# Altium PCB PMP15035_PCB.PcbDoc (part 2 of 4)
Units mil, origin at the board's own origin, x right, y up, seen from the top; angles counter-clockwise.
Board outline 5645 x 4585 mil, 8 copper layers (Top Layer, Signal Layer 1, Signal Layer 2, Signal Layer 3, Signal Layer 4, Signal Layer 5, Signal Layer 6, Bottom Layer), stack 60.9 mil thick; 335 components, 164 nets, 981 pads, 1349 vias.
Unrouted connection lines stored in the file: 46.
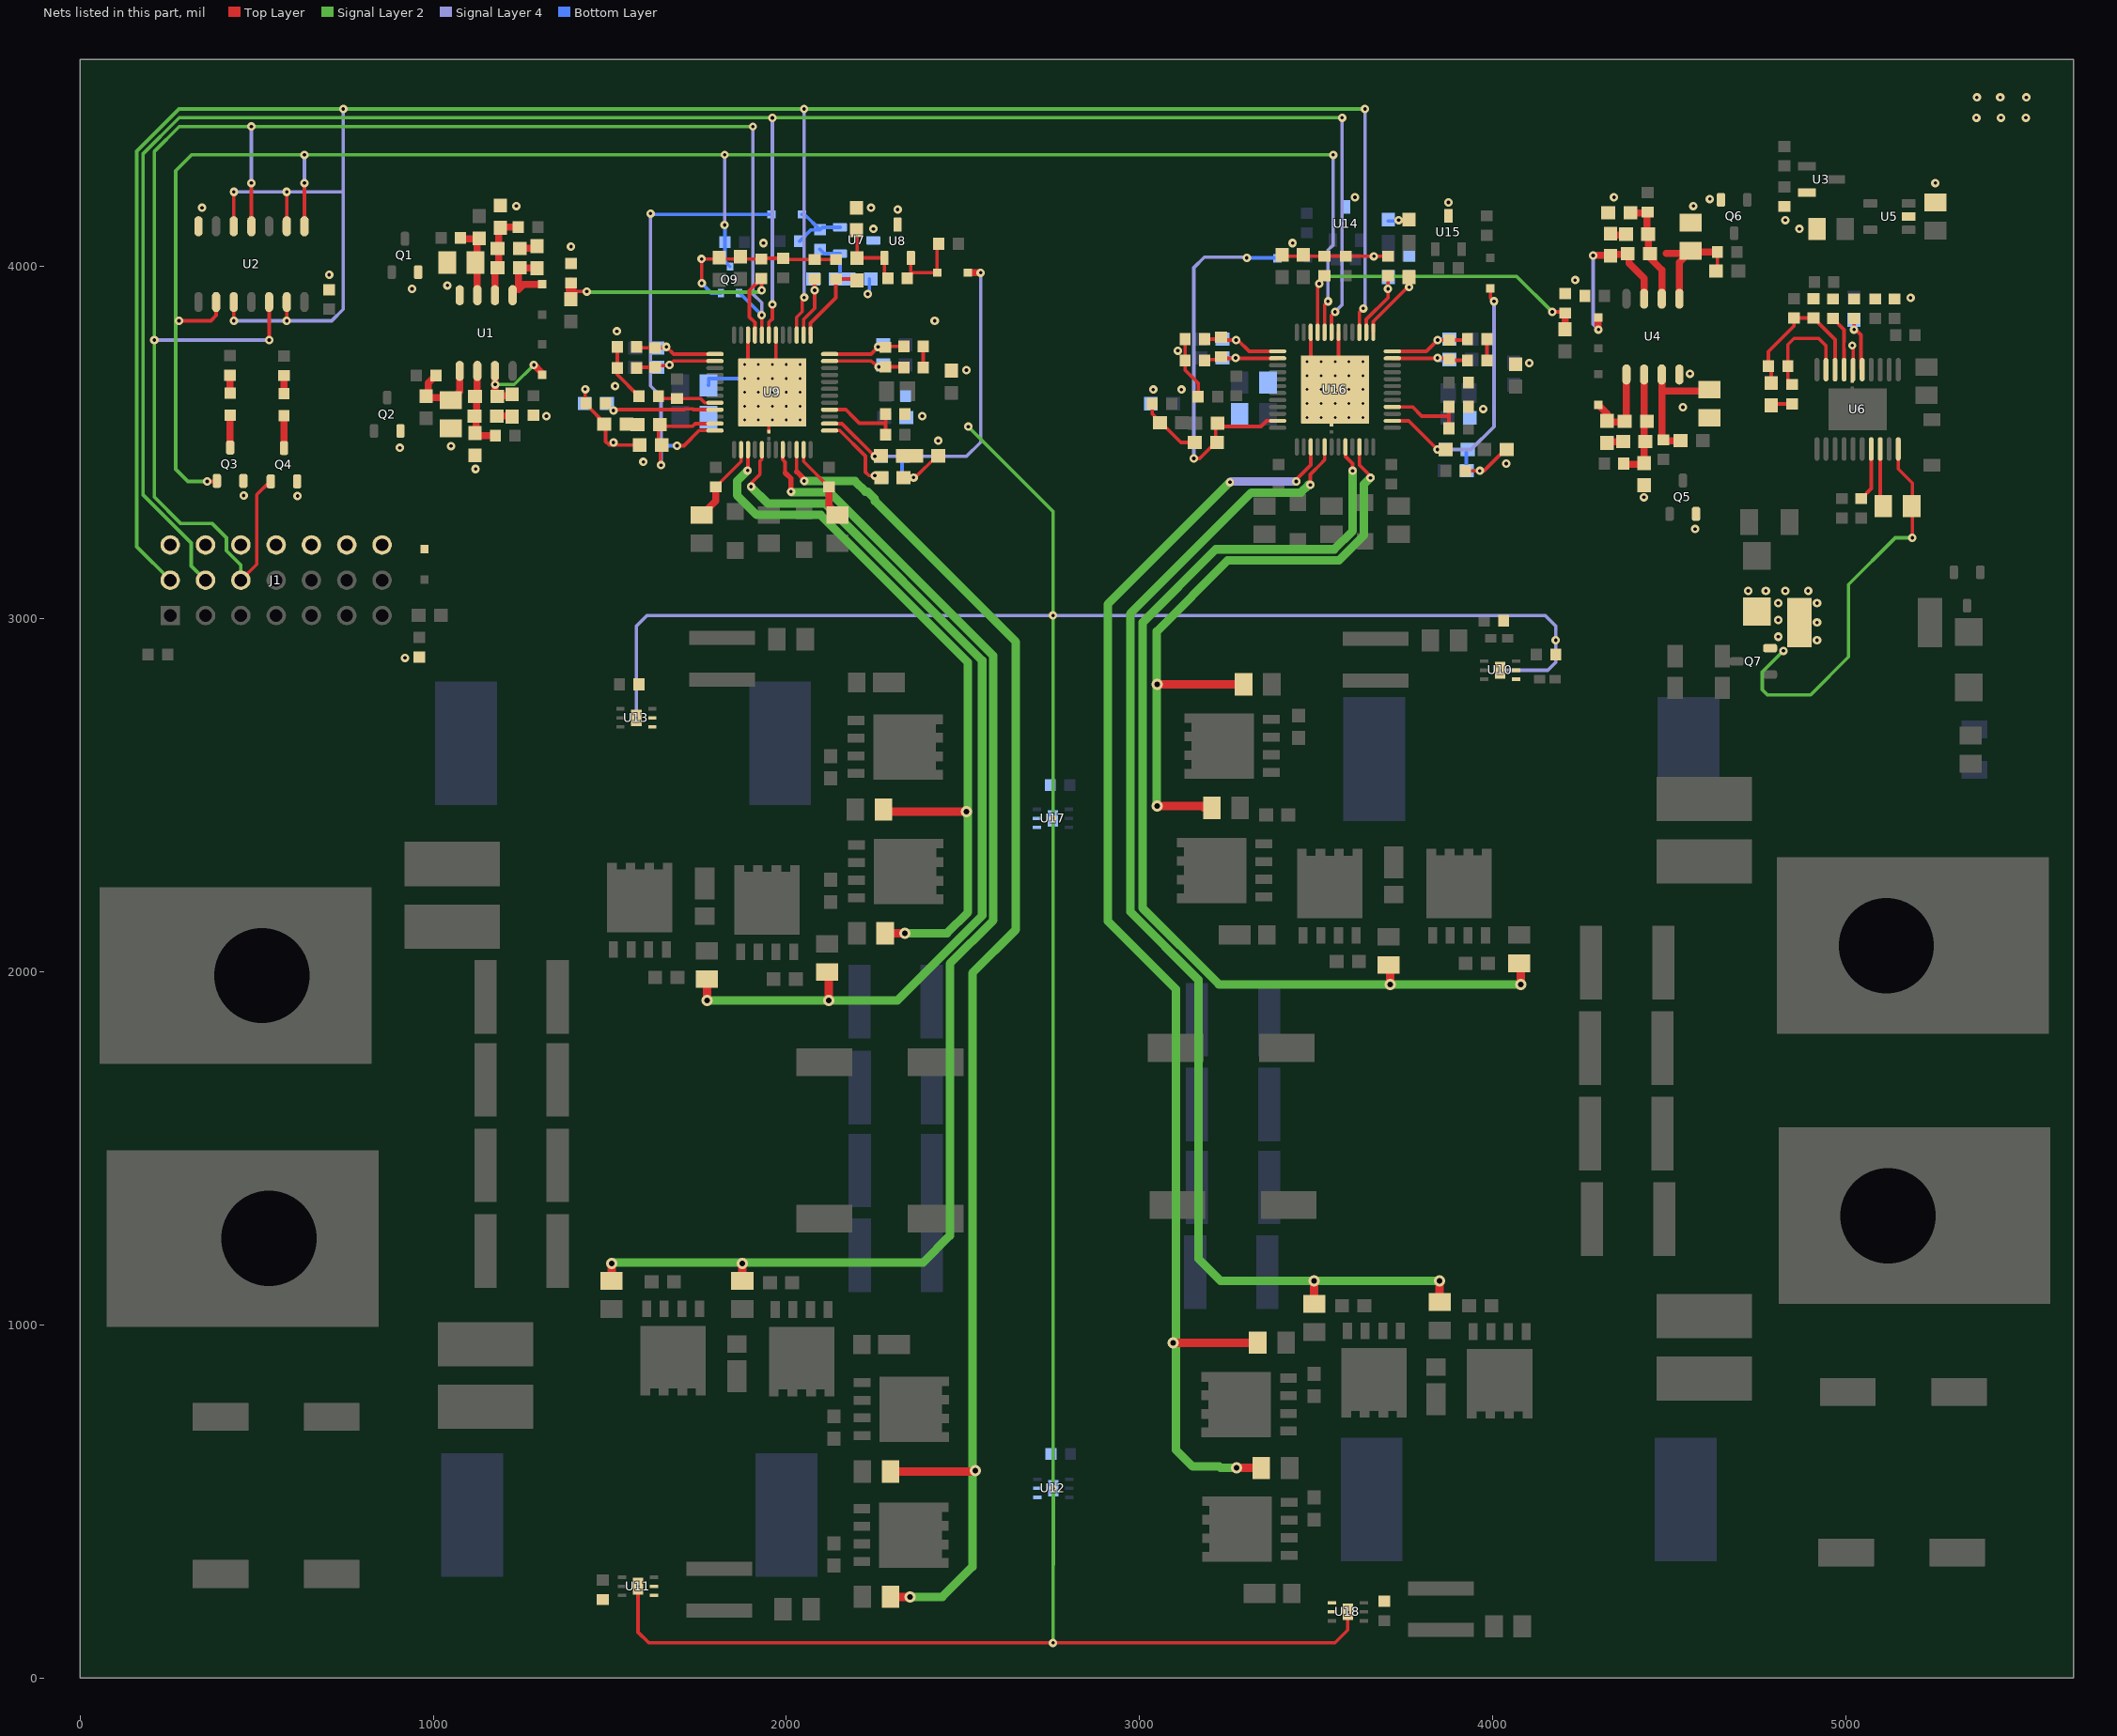
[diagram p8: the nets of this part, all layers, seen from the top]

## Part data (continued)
C8 C30 C31 C32 C36 C61 C62 C63 C66: library part CMP-0006993-4, "CAP, CERM, 1000 pF, 100 V, +/- 5%, C0G/NP0, 0603", Cap_Case=0603, Manufacturer=TDK, Supplier Part Number 1=445-2312-1-ND, TempCo=C0G/NP0, Tolerance_%=5%, Value1="0.0589 ohm", Value2=100V, ValueDisplayed=1000pF
C16 C17 C37 C38 C68 C69: "CAP, CERM, 1 µF, 100 V, +/- 10%, X7S, 0805", Cap_Case=0805, Manufacturer=TDK, Supplier Part Number 1=445-5205-1-ND, TempCo=X7S, Tolerance_%=10, Value1=Unknown, Value2=100V, ValueDisplayed=1µF
C18 C19: library part CMP-0009015-2, "CAP, CERM, 10 uF, 50 V, +/- 10%, X5R, AEC-Q200 Grade 1, 1206", Cap_Case=1206, Manufacturer=MuRata, Supplier Part Number 1=490-12456-1-ND, TempCo=X5R, Tolerance_%=10%, Value1=Unknown, Value2=50V, ValueDisplayed=10uF
C20 C21: library part CMP-0007886-2, "CAP, CERM, 0.1 uF, 100 V, +/- 10%, X7R, 0805", Cap_Case=0805, Manufacturer=TDK, Supplier Part Number 1=445-1418-1-ND, TempCo=X7R, Tolerance_%=10%, Value1="0.020726 ohm", Value2=100V, ValueDisplayed=0.1uF
C22 C45 C75: library part CMP-0007867-2, "CAP, CERM, 2.2 uF, 16 V, +/- 10%, X7R, 0805", Cap_Case=0805, Manufacturer=TDK, Supplier Part Number 1=445-1420-1-ND, TempCo=X7R, Tolerance_%=10%, Value1="0.0049 ohm", Value2=16V, ValueDisplayed=2.2uF
C23: library part CMP-0008653-2, "CAP, CERM, 47 uF, 16 V, +/- 15%, X5R, 1206", Cap_Case=1206, Manufacturer=TDK, Supplier Part Number 1=445-6003-1-ND, TempCo=X5R, Tolerance_%=15%, Value1=Unknown, Value2=16V, ValueDisplayed=47uF
C24: library part CMP-0007124-4, "CAP, CERM, 1800 pF, 25 V, +/- 10%, X7R, AEC-Q200 Grade 1, 0603", Cap_Case=0603, Manufacturer=MuRata, Supplier Part Number 1=81-GCJ216R71E182KA1D, TempCo=X7R, Tolerance_%=10%, Value1=Unknown, Value2=25V, ValueDisplayed=1800pF
C26: library part CMP-0007212-4, "CAP, CERM, 360 pF, 50 V, +/- 5%, C0G/NP0, 0603", Cap_Case=0603, Manufacturer=MuRata, Supplier Part Number 1=490-1440-1-ND, TempCo=C0G/NP0, Tolerance_%=5%, Value1=Unknown, Value2=50V, ValueDisplayed=360pF
C27 C28 C46 C77: "CAP, CERM, 1 µF, 25 V, +/- 10%, X7R, 0603", Cap_Case=0603, Manufacturer=MuRata, Supplier Part Number 1=490-5307-1-ND, TempCo=X7R, Tolerance_%=10, Value1=Unknown, Value2=25V, ValueDisplayed=1µF
C29: library part CMP-0007080-5, "CAP, CERM, 0.068 uF, 50 V, +/- 10%, X7R, AEC-Q200 Grade 1, 0603", Cap_Case=0603, Manufacturer=TDK, Supplier Part Number 1=445-5665-1-ND, TempCo=X7R, Tolerance_%=10%, Value1="0.035979 ohm", Value2=50V, ValueDisplayed=0.068uF
C33 C58 C64 C88: library part CMP-0006834-5, "CAP, CERM, 470 pF, 50 V, +/- 10%, X7R, 0603", Cap_Case=0603, Manufacturer="Wurth Elektronik", Supplier Part Number 1=710-885012206081, TempCo=X7R, Tolerance_%=10%, Value1=Unknown, Value2=50V, ValueDisplayed=470pF
C34 C54 C65 C85: library part CMP-0007423-4, "CAP, CERM, 0.047 uF, 25 V, +/- 10%, X7R, 0603", Cap_Case=0603, Manufacturer=MuRata, Supplier Part Number 1=490-1522-1-ND, TempCo=X7R, Tolerance_%=10%, Value1=Unknown, Value2=25V, ValueDisplayed=0.047uF
C35 C49 C50 C59 C67 C79 C80 C89: "CAP, CERM, 0.01 µF, 100 V, +/- 10%, X7R, 0603", Cap_Case=0603, Manufacturer=AVX, Supplier Part Number 1=478-1205-1-ND, TempCo=X7R, Tolerance_%=10, Value1="0.098 ohm", Value2=100V, ValueDisplayed=0.01µF
C39 C51 C70 C82: "CAP, CERM, 0.47 µF, 16 V, +/- 10%, X7R, 0603", Cap_Case=0603, Manufacturer=MuRata, Supplier Part Number 1=490-3295-1-ND, TempCo=X7R, Tolerance_%=10, Value1=Unknown, Value2=16V, ValueDisplayed=0.47µF
C40 C41 C52 C53 C56 C57 C60 C71 C72 C83 C84 C86 C87: "CAP, CERM, 100 pF, 50 V, +/- 5%, C0G/NP0, 0603", Cap_Case=0603, Manufacturer=Kemet, Supplier Part Number 1=399-1061-1-ND, TempCo=C0G/NP0, Tolerance_%=5, Value1=Unknown, Value2=50V, ValueDisplayed=100pF
C43 C48 C73 C78: "CAP, CERM, 0.22 µF, 50 V, +/- 10%, X7R, 0603", Cap_Case=0603, Manufacturer=TDK, Supplier Part Number 1=445-7408-1-ND, TempCo=X7R, Tolerance_%=10, Value1=Unknown, Value2=50V, ValueDisplayed=0.22µF
C92 C93 C110 C111: "CAP, CERM, 100 pF, 100 V, +/- 10%, C0G/NP0, 0805", Cap_Case=0805, Manufacturer=AVX, Supplier Part Number 1=478-3733-1-ND, TempCo=C0G/NP0, Tolerance_%=10, Value1="0.356 ohm", Value2=100V, ValueDisplayed=100pF
C94 C95 C96 C97 C102 C103 C104 C105 C112 C114 C115 C127: library part CMP-0012273-3, "CAP, Aluminum Polymer, 180 uF, 50 V, +/- 20%, 0.019 ohm, SMD, 2-Leads, Dia 10.5mm, Pin Spacing 8mm SMD", Cap_Case=10x12.7mm, Manufacturer=Nichicon, Supplier Part Number 1=493-13774-1-ND, Tolerance_%=20%, Value1="0.019 ohm", Value2=50V, ValueDisplayed=180uF
C98 C99 C100 C101 C106 C107 C108 C109 C116 C117 C118 C119 C121 C122 C123 C126: library part CMP-0009385-2, "CAP, CERM, 4.7 uF, 100 V, +/- 20%, X7R, 2220", Cap_Case=2220, Manufacturer=TDK, Supplier Part Number 1=445-1450-1-ND, TempCo=X7R, Tolerance_%=20%, Value1="0.0015 ohm", Value2=100V, ValueDisplayed=4.7uF
D1 D2 D5 D6 D10 D11 D16 D17: "Diode, Ultrafast, 75 V, 0.25 A, SOD-323", Manufacturer="Central Semiconductor", Value1=0.25A, Value2=1.2V
D7: library part CMP-0076974-1, "Diode, Switching, 100 V, 0.15 A, SOD-123", Manufacturer="Micro Commercial Components", Supplier Part Number 1=1N4148WTPMSCT-ND, Value1=0.15A, Value2=1.25V
D8 D9: library part CMP-0028585-1, "Diode, Schottky, 60 V, 1 A, SMA", Manufacturer="ON Semiconductor", Supplier Part Number 1=SS16T3GOSCT-ND, Value1=1A, Value2=0.72V
D12 D13 D18 D19: "Diode, Schottky, 60 V, 1 A, SOD-123F", Manufacturer="NXP Semiconductor", Supplier Part Number 1=568-4104-1-ND, Value1=1A, Value2=0.57V
D14: "Diode, Switching, 75 V, 0.3 A, SOD-523", Manufacturer="Micro Commercial Components", Supplier Part Number 1=1N4148XTPMSCT-ND, Value1=0.3A, Value2=1.25V
D15: library part CMP-0005865-1, "Diode, Zener, 5.1 V, 200 mW, SOD-323", Manufacturer="Diodes Inc.", Power_W=200mW, Supplier Part Number 1=BZT52C5V1S-FDICT-ND, Value1=0.2W
D21 D22 D23 D24 D25 D26 D27 D28: library part CMP-0028825-1, "Diode, Schottky, 60 V, 3 A, AEC-Q101, SOD-123HE", Manufacturer="Fairchild Semiconductor", Supplier Part Number 1=FSV360FPCT-ND, Value1=3A, Value2=0.65V
J1: library part CMP-0055099-1, "Header, 2.54 mm, 7x3, Gold, Vertical, TH", Color=Black, Manufacturer=Mill-Max, Supplier Part Number 1=ED8040-21-ND
L1: library part CMP-0061858-2, "Inductor, Shielded Drum Core, Ferrite, 150 uH, 1.16 A, 0.37 ohm, SMD", Manufacturer=Coilcraft, Value1="0.37 ohm", Value2=1.16A, ValueDisplayed=150uH
L8 L9 L10 L11: Alternate Manufacturer=-, Manufacturer="Used in BOM report"
NT1 NT2 NT3: "Single point connection between nets."
PGND PGND V12_A V12_B: "Terminal 70A Lug", Manufacturer=Panduit, Supplier Part Number 1=CXS70-14-C-ND
Q1 Q2 Q3 Q4 Q5 Q6: "MOSFET, N-CH, 60 V, 0.24 A, SOT-23", Alternate Manufacturer=None, Manufacturer=Vishay-Siliconix, Supplier Part Number 1=2N7002E-T1-E3CT-ND, Value1="1.8 ohm", Value2="0.4 nC"
Q7 Q8: library part CMP-0079125-1, "MOSFET, N-CH, 60 V, 2.3 A, AEC-Q101, SOT-23", Alternate Manufacturer=None, Manufacturer="Infineon Technologies", Supplier Part Number 1=BSR606NH6327XTSA1CT-ND, Value1="0.09 ohm", Value2="3.7 nC"
Q9: library part CMP-0000948-2, "MOSFET, N-CH, 100 V, 0.17 A, SOT-323", Alternate Manufacturer=None, Manufacturer="Diodes Inc.", Supplier Part Number 1=BSS123W-FDICT-ND, Value1=1
Q10 Q11 Q12 Q13 Q14 Q15 Q16 Q17 Q18 Q19 Q20 Q21 Q22 Q23 Q24 Q25: "MOSFET N-CH 60V SO8FL", Alternate Manufacturer=-, Input Capacitance=3.6nF, Manufacturer="Used in BOM report", Max Operating Temperature=175°C, Max Power Dissipation=3.7W, Min Operating Temperature=-55°C, Supplier Part Number 1=NVMFS5C628NLT1G**MULT1
R1 R17: library part CMP-0022841-3, "RES, 17.8 k, 1%, 0.1 W, 0603", Manufacturer="Yageo America", Power_W=100mW, Supplier Part Number 1=311-17.8KHRCT-ND, TempCo="200 ppm/C", Tolerance_%=1%, Value2=0.1W, Value_Code=17k8, ValueDisplayed=17.8k
R2 R16: library part CMP-0022360-3, "RES, 37.4 k, 1%, 0.1 W, 0603", Manufacturer=Vishay-Dale, Power_W=100mW, Supplier Part Number 1=541-37.4KHCT-ND, TempCo="100 ppm/C", Tolerance_%=1%, Value2=0.1W, Value_Code=37k4, ValueDisplayed=37.4k
R3 R19: library part CMP-0022986-3, "RES, 2.20 k, 1%, 0.1 W, 0603", Manufacturer="Yageo America", Power_W=100mW, Supplier Part Number 1=311-2.20KHRCT-ND, TempCo="200 ppm/C", Tolerance_%=1%, Value2=0.1W, Value_Code=2k20, ValueDisplayed=2.20k
R4 R18: library part CMP-0023279-3, "RES, 7.50 k, 1%, 0.1 W, 0603", Manufacturer="Yageo America", Power_W=100mW, Supplier Part Number 1=311-7.50KHRCT-ND, TempCo="200 ppm/C", Tolerance_%=1%, Value2=0.1W, Value_Code=7k50, ValueDisplayed=7.50k
R5 R21: library part CMP-0023332-3, "RES, 9.09 k, 1%, 0.1 W, 0603", Manufacturer="Yageo America", Power_W=100mW, Supplier Part Number 1=311-9.09KHRCT-ND, TempCo="200 ppm/C", Tolerance_%=1%, Value2=0.1W, Value_Code=9k09, ValueDisplayed=9.09k
R6 R20: library part CMP-0023195-3, "RES, 59.0 k, 1%, 0.1 W, 0603", Manufacturer="Yageo America", Power_W=100mW, Supplier Part Number 1=311-59.0KHRCT-ND, TempCo="200 ppm/C", Tolerance_%=1%, Value2=0.1W, Value_Code=59k0, ValueDisplayed=59.0k
R7 R22: library part CMP-0023141-3, "RES, 499, 1%, 0.1 W, 0603", Manufacturer="Yageo America", Power_W=100mW, Supplier Part Number 1=311-499HRCT-ND, TempCo="200 ppm/C", Tolerance_%=1%, Value2=0.1W, Value_Code=499R, ValueDisplayed=499
R8 R9 R23 R24: library part CMP-0022901-2, "RES, 200 k, 1%, 0.1 W, 0603", Manufacturer="Yageo America", Power_W=100mW, Supplier Part Number 1=311-200KHRCT-ND, TempCo="200 ppm/C", Tolerance_%=1%, Value2=0.1W, Value_Code=200k
R10 R25 R54 R79: "RES, 10.0 k, 1%, 0.1 W, 0603", Manufacturer=Vishay-Dale, Power_W=0.1, Supplier Part Number 1=541-10.0KHCT-ND, TempCo="100 ppm/C", Tolerance_%=1, Value1=1%, Value2=0.1W, Value_Code=10k0, ValueDisplayed=10.0k
R11 R12 R27 R28: "RES, 20.0, 1%, 0.1 W, 0603", Manufacturer=Vishay-Dale, Power_W=0.1, Supplier Part Number 1=541-20.0HCT-ND, TempCo="100 ppm/C", Tolerance_%=1, Value1=1%, Value2=0.1W, Value_Code=20R0, ValueDisplayed=20.0
R13 R14 R15 R40 R42 R66 R68: "RES, 4.99 k, 1%, 0.1 W, 0603", Manufacturer=Vishay-Dale, Power_W=0.1, Supplier Part Number 1=541-4.99KHCT-ND, TempCo="100 ppm/C", Tolerance_%=1, Value1=1%, Value2=0.1W, Value_Code=4k99, ValueDisplayed=4.99k
R30: "RES, 75.0 k, 1%, 0.1 W, 0603", Manufacturer=Vishay-Dale, Power_W=0.1, Supplier Part Number 1=541-75.0KHCT-ND, TempCo="100 ppm/C", Tolerance_%=1, Value1=1%, Value2=0.1W, Value_Code=75k0, ValueDisplayed=75.0k
R31: "RES, 29.4 k, 1%, 0.1 W, 0603", Manufacturer=Vishay-Dale, Power_W=0.1, Supplier Part Number 1=541-29.4KHCT-ND, TempCo="100 ppm/C", Tolerance_%=1, Value1=1%, Value2=0.1W, Value_Code=29k4, ValueDisplayed=29.4k
R32: library part CMP-0022866-3, "RES, 1.07 k, 1%, 0.1 W, 0603", Manufacturer="Yageo America", Power_W=100mW, Supplier Part Number 1=311-1.07KHRCT-ND, TempCo="200 ppm/C", Tolerance_%=1%, Value2=0.1W, Value_Code=1k07, ValueDisplayed=1.07k
R33: "RES, 18.2 k, 1%, 0.1 W, 0603", Manufacturer=Vishay-Dale, Power_W=0.1, Supplier Part Number 1=541-18.2KHCT-ND, TempCo="100 ppm/C", Tolerance_%=1, Value1=1%, Value2=0.1W, Value_Code=18k2, ValueDisplayed=18.2k
R34: library part CMP-0079171-1, "RES, 0.22, 1%, 0.5 W, 1206", Manufacturer="Susumu Co Ltd", Power_W=500mW, Supplier Part Number 1=28K1709, TempCo="100 ppm/C", Tolerance_%=1%, Value2=0.5W, Value_Code=R220, ValueDisplayed=0.22
R35: library part CMP-0022850-3, "RES, 18.2 k, 1%, 0.1 W, 0603", Manufacturer="Yageo America", Power_W=100mW, Supplier Part Number 1=311-18.2KHRCT-ND, TempCo="200 ppm/C", Tolerance_%=1%, Value2=0.1W, Value_Code=18k2, ValueDisplayed=18.2k
R36: "RES, 732, 1%, 0.1 W, 0603", Manufacturer=Vishay-Dale, Power_W=0.1, Supplier Part Number 1=541-732HCT-ND, TempCo="100 ppm/C", Tolerance_%=1, Value1=1%, Value2=0.1W, Value_Code=732R, ValueDisplayed=732
R37: "RES, 5.23 k, 1%, 0.1 W, 0603", Manufacturer=Vishay-Dale, Power_W=0.1, Supplier Part Number 1=541-5.23KHCT-ND, TempCo="100 ppm/C", Tolerance_%=1, Value1=1%, Value2=0.1W, Value_Code=5k23, ValueDisplayed=5.23k
R38: "RES, 10.0, 1%, 0.1 W, 0603", Manufacturer=Vishay-Dale, Power_W=0.1, Supplier Part Number 1=541-10.0HCT-ND, TempCo="100 ppm/C", Tolerance_%=1, Value1=1%, Value2=0.1W, Value_Code=10R0, ValueDisplayed=10.0
R39 R45 R65 R71: "RES, 95.3 k, 1%, 0.1 W, 0603", Manufacturer=Vishay-Dale, Power_W=0.1, Supplier Part Number 1=541-95.3KHCT-ND, TempCo="100 ppm/C", Tolerance_%=1, Value1=1%, Value2=0.1W, Value_Code=95k3, ValueDisplayed=95.3k
R41 R43 R67 R69: library part CMP-0022991-3, "RES, 2.40 k, 1%, 0.1 W, 0603", Manufacturer="Yageo America", Power_W=100mW, Supplier Part Number 1=311-2.40KHRCT-ND, TempCo="200 ppm/C", Tolerance_%=1%, Value2=0.1W, Value_Code=2k40, ValueDisplayed=2.40k
R44 R62 R70 R86: library part CMP-0022883-3, "RES, 1.50 k, 1%, 0.1 W, 0603", Manufacturer="Yageo America", Power_W=100mW, Supplier Part Number 1=311-1.50KHRCT-ND, TempCo="200 ppm/C", Tolerance_%=1%, Value2=0.1W, Value_Code=1k50, ValueDisplayed=1.50k
R46 R47 R72 R73: library part CMP-0022999-3, "RES, 2.94 k, 1%, 0.1 W, 0603", Manufacturer="Yageo America", Power_W=100mW, Supplier Part Number 1=311-2.94KHRCT-ND, TempCo="200 ppm/C", Tolerance_%=1%, Value2=0.1W, Value_Code=2k94, ValueDisplayed=2.94k
R48 R49 R63 R74 R75: library part CMP-0022906-3, "RES, 20.0 k, 1%, 0.1 W, 0603", Manufacturer="Yageo America", Power_W=100mW, Supplier Part Number 1=311-20.0KHRCT-ND, TempCo="200 ppm/C", Tolerance_%=1%, Value2=0.1W, Value_Code=20k0, ValueDisplayed=20.0k
R50: "RES, 100 k, 1%, 0.063 W, 0402", Manufacturer=Vishay-Dale, Power_W=0.063, Supplier Part Number 1=541-100KLCT-ND, TempCo="100 ppm/C", Tolerance_%=1, Value1=1%, Value2=0.063W, Value_Code=100k
R51: "RES, 49.9 k, 1%, 0.1 W, 0603", Manufacturer=Vishay-Dale, Power_W=0.1, Supplier Part Number 1=541-49.9KHCT-ND, TempCo="100 ppm/C", Tolerance_%=1, Value1=1%, Value2=0.1W, Value_Code=49k9, ValueDisplayed=49.9k
R52 R76: library part CMP-0023336-3, "RES, 9.76 k, 1%, 0.1 W, 0603", Manufacturer="Yageo America", Power_W=100mW, Supplier Part Number 1=311-9.76KHRCT-ND, TempCo="200 ppm/C", Tolerance_%=1%, Value2=0.1W, Value_Code=9k76, ValueDisplayed=9.76k
R53 R58 R77 R83: library part CMP-0021913-2, "RES, 2.00, 1%, 0.125 W, 0805", Manufacturer="Yageo America", Power_W=125mW, Supplier Part Number 1=311-2.00CRCT-ND, TempCo="200 ppm/C", Tolerance_%=1%, Value2=0.125W, Value_Code=2R00, ValueDisplayed=2.00
R55 R80: library part CMP-0023098-3, "RES, 40.2 k, 1%, 0.1 W, 0603", Manufacturer="Yageo America", Power_W=100mW, Supplier Part Number 1=311-40.2KHRCT-ND, TempCo="200 ppm/C", Tolerance_%=1%, Value2=0.1W, Value_Code=40k2, ValueDisplayed=40.2k
R56 R81: "RES, 24.9, 1%, 0.125 W, 0805", Manufacturer=Vishay-Dale, Power_W=0.125, Supplier Part Number 1=541-24.9CCT-ND, TempCo="100 ppm/C", Tolerance_%=1, Value1=1%, Value2=0.125W, Value_Code=24R9, ValueDisplayed=24.9
R57 R82: library part CMP-0023263-3, "RES, 73.2 k, 1%, 0.1 W, 0603", Manufacturer="Yageo America", Power_W=100mW, Supplier Part Number 1=311-73.2KHRCT-ND, TempCo="200 ppm/C", Tolerance_%=1%, Value2=0.1W, Value_Code=73k2, ValueDisplayed=73.2k
R59 R64: library part CMP-0022744-3, "RES, 10.5 k, 1%, 0.1 W, 0603", Manufacturer="Yageo America", Power_W=100mW, Supplier Part Number 1=311-10.5KHRCT-ND, TempCo="200 ppm/C", Tolerance_%=1%, Value2=0.1W, Value_Code=10k5, ValueDisplayed=10.5k
R60 R84: library part CMP-0023318-3, "RES, 91.0 k, 1%, 0.1 W, 0603", Manufacturer="Yageo America", Power_W=100mW, Supplier Part Number 1=311-91.0KHRCT-ND, TempCo="200 ppm/C", Tolerance_%=1%, Value2=0.1W, Value_Code=91k0, ValueDisplayed=91.0k
R61 R85: library part CMP-0023019-3, "RES, 30.9 k, 1%, 0.1 W, 0603", Manufacturer="Yageo America", Power_W=100mW, Supplier Part Number 1=311-30.9KHRCT-ND, TempCo="200 ppm/C", Tolerance_%=1%, Value2=0.1W, Value_Code=30k9, ValueDisplayed=30.9k
R87 R99 R111 R123: library part CMP-0015025-2, "RES, 0.001, 1%, 4 W, RES_2725", Manufacturer="Stackpole Electronics Inc", Power_W=4W, Supplier Part Number 1=CSS2725FT1L00CT-ND, TempCo="50 ppm/C", Tolerance_%=1%, Value_Code=1L000, ValueDisplayed=0.001
R88 R90 R91 R97 R100 R104 R105 R109: library part CRCW080549K9FKEA, "RES, 49.9 k, 1%, 0.125 W, 0805", Manufacturer=Vishay-Dale, Power_W=0.125, Supplier Part Number 1=541-49.9KCCT-ND, TempCo="100 ppm/C", Tolerance_%=1, Value1=1%, Value2=0.125W, Value_Code=49k9, ValueDisplayed=49.9k
R89 R101 R113 R125: "RES, 10.0, 1%, 1 W, 1218", Manufacturer=Vishay-Dale, Power_W=1, TempCo="100 ppm/C", Value1=1%, Value2=1W, Value_Code=10R0, ValueDisplayed=10.0
R92 R93 R102 R103 R116 R117 R126 R127: library part CMP-0022900-2, "RES, 1.00, 1%, 0.1 W, 0603", Manufacturer="Yageo America", Power_W=100mW, Supplier Part Number 1=311-1.00HRCT-ND, TempCo="200 ppm/C", Tolerance_%=1%, Value2=0.1W, Value_Code=1R00, ValueDisplayed=1.00
R94 R95 R96 R98 R106 R107 R108 R110 R118 R119 R120 R122 R130 R131 R132 R134: "RES, 1.00, 1%, 0.125 W, 0805", Manufacturer=Vishay-Dale, Power_W=0.125, Supplier Part Number 1=71-CRCW0805-1-E3, TempCo="100 ppm/C", Tolerance_%=1, Value1=1%, Value2=0.125W, Value_Code=1R00, ValueDisplayed=1.00
R112 R114 R115 R121 R124 R128 R129 R133: library part CMP-0022447-4, "RES, 49.9 k, 1%, 0.1 W, AEC-Q200 Grade 0, 0603", Manufacturer=Vishay-Dale, Power_W=100mW, Supplier Part Number 1=541-49.9KHCT-ND, TempCo="100 ppm/C", Tolerance_%=1%, Value2=0.1W, Value_Code=49k9, ValueDisplayed=49.9k
U1 U4: "17MHz Rail-to-Rail Input and Output Op Amp, D0008A", Alternate Manufacturer="Texas Instruments"
U2: library part CMP-0052884-1, "Quadruple 2-Input Positive-NAND Gates, D0014A, LARGE T&R", F @ Nom Voltage(Max)(Mhz)=70, Generic Part Number=SN74LV00A, ICC @ Nom Voltage(Max)(mA)=0.02, Manufacturer="Texas Instruments", Operating Temperature Range(C)="-40 to 125,-40 to 85", Rating=Catalog, tpd @ Nom Voltage(Max)(ns)=20,13,8.5, Voltage(Nom)(V)=2.5,3.3,5
U3: "Precision Micropower Shunt Voltage Reference, 3-pin SOT-23", Manufacturer="Texas Instruments", PackageTopMarking=RJA*XTT, PowerWise=N, Supplier Part Number 1=LM4040AIM3X-2.0-ND
U5: "150-mA, 30-V, 1-uA IQ Voltage Regulators with Enable, DBV0005A", Alternate Manufacturer="Texas Instruments", Alternate PartNumber=TPS70950DBVT
U6: "Wide Voltage Range Buck-Boost Controller, 20-pin TSSOP-EP, Pb-Free", Manufacturer="Texas Instruments", PackageTopMarking=NSUZXYTT*LM5118*MH, PowerWise=Y, Supplier Part Number 1=LM5118MH-ND
U7 U8 U14 U15: library part CMP-0071728-1, "Low-Voltage (1.24V) Adjustable Precision Shunt Regulators, 3-pin SOT-23, Pb-Free", Manufacturer="Texas Instruments", PackageTopMarking=RLB*XTT, PowerWise=N
U9 U16: library part LM5170_PreIC, "IC, Controller, Bi-Directional", Alternate Manufacturer=-, Manufacturer="Texas Instruments"
U10 U11 U12 U13 U17 U18: "1.6V Factory Preset Temperature Switch and Temperature Sensor, 6-pin LLP, Pb-Free", Manufacturer="Texas Instruments", PackageTopMarking=XTT*145, PowerWise=Y, Supplier Part Number 1=LM26LVCISD-145/NOPBTR-ND

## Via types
v1: diameter 24, hole 10, Top Layer to Bottom Layer, tented both sides, 873 vias
v2: diameter 32, hole 16, Top Layer to Bottom Layer, 237 vias
v3: diameter 24, hole 10, Top Layer to Bottom Layer, 145 vias
v4: diameter 19.68, hole 7.87, Top Layer to Bottom Layer, 62 vias
v5: diameter 32, hole 16, Top Layer to Bottom Layer, tented both sides, 14 vias
v6: diameter 23, hole 10, Top Layer to Bottom Layer, tented both sides, 5 vias
v7: diameter 19.68, hole 7.87, Top Layer to Bottom Layer, tented top, 4 vias
v8: diameter 19.68, hole 7.87, Top Layer to Bottom Layer, tented bottom, 2 vias
v9: diameter 40, hole 20, Top Layer to Bottom Layer, tented both sides, 2 vias
v10: diameter 24, hole 10, Top Layer to Bottom Layer, tented bottom, 2 vias
v11: diameter 22, hole 10, Top Layer to Bottom Layer, tented both sides, 1 vias
v12: diameter 24/24/24/24/24/24/24/24 (per signal layer), hole 10, Top Layer to Bottom Layer, tented both sides, 1 vias
v13: diameter 26, hole 10, Top Layer to Bottom Layer, tented both sides, 1 vias

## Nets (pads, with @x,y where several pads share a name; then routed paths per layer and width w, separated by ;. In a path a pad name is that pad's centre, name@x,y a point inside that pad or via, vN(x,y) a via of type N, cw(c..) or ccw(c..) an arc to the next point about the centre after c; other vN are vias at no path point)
AGND: C1.2 C6.2 C7.2 C8.2 C9.2 C14.2 C15.2 C16.2 C17.2 C25.2 C26.2 C32.2 C33.1 C35.2 C36.2 C37.2 C38.2 C40.2 C41.2 C42.2 C44.2 C46.2 C47.2 C49.2 C50.2 C52.2 C53.2 C55.2 C56.2 C57.2 C58.2 C59.2 C60.2 C61.2 C64.1 C66.2 C67.2 C68.2 C69.2 C71.2 C72.2 C74.2 C76.2 C77.2 C79.2 C80.2 C83.2 C84.2 C86.2 C87.2 C88.2 C89.2 C120.2 D15.2 J1.3 J1.6 J1.9 J1.12 J1.15 J1.18 J1.21 NT1.1 NT2.1 NT3.1 Q1.2 Q2.2 Q3.2 Q4.2 Q5.2 Q6.2 Q9.2 R3.1 R4.1 R10.2 R18.1 R19.1 R25.2 R31.1 R33.1 R36.1 R44.2 R46.1 R47.1 R48.2 R52.2 R54.1 R55.1 R57.1 R60.1 R61.1 R62.1 R64.1 R70.2 R72.1 R73.1 R74.2 R76.2 R79.1 R80.1 R82.1 R84.1 R85.1 R86.1 U1.4 U2.7 U3.2 U4.4 U5.2 U6.6 U7.3 U8.3 U9.42 U9.46 U9.49 U10.1 U10.2 U10.7 U11.1 U11.2 U11.7 U12.1 U12.2 U12.7 U13.1 U13.2 U13.7 U14.3 U15.3 U16.42 U16.46 U16.49 U17.1 U17.2 U17.7 U18.1 U18.2 U18.7 | length 11996.8
  Top Layer w10: C56.2@1430.16,3610.22 v1(1430.16,3650.94) ; C56.2@1432.6,3610.95 1432.6,3607.78 1488.17,3552.2 1488.17,3502.93 1498.23,3492.87 C58.2@1584.23,3492.87 C58.2@1588.17,3492.87 ; C53.2@1520.95,3770.55 C52.2@1520.95,3710.55 1520.95,3692.6 C36.2@1582.6,3630.94 ; v7(1580,260) 1580,129.87 1610,99.87 v1(2755,99.87) 3553.75,99.87 3589.77,135.9 v7(3589.77,187.56) ; v1(1760.16,3950.94) 1760.16,4010.94 1768.98,4019.76 1809.53,4019.76 1869.53,4019.76 C49.2@1929.53,4019.76 1931.2,4021.44 R54.1@1990.85,4021.44 1993.78,4018.5 C59.2@2080.16,4018.5 C35.2@2140.16,4018.5 ; U9.49@1891.26,3711.1 U9.46@1891.26,3804.61 ; NT2.1@1950.16,3530.94 U9.49@1950.16,3553.46 ; U9.49@1970,3652.05 U9.42@1970,3804.61 ; R61.1@2327.72,3400.94 R61.1@2331.65,3400.94 v1(2360.16,3400.94) 2365.16,3400.94 R44.2@2426.42,3462.2 ; C41.2@2387.72,3712.2 C40.2@2387.72,3772.2 ; C86.2@3036.19,3610 3036.19,3581.26 3117.45,3500 C88.2@3156.5,3500 C88.2@3160.44,3500 ; C84.2@3128.98,3792.8 C83.2@3128.98,3732.8 3128.98,3704.76 3166.19,3667.56 C66.2@3166.19,3630 ; R76.2@3403.75,4027.56 3463.75,4027.56 v1(3663.75,4027.56) C89.2@3704.24,4027.56 ; U16.49@3484.85,3738.58 U16.46@3484.85,3812.4 ; NT3.1@3543.75,3550 3543.75,3640 v4(3553.75,3650) ; U16.49@3563.59,3659.84 U16.42@3563.59,3812.4 ; v1(3733.75,4130) R73.1@3761.31,4130 ; C87.2@3922.61,3420 v1(3963.75,3420) 3975.76,3420 R70.2@4035.76,3480 ; C72.2@3984.11,3732.8 C71.2@3984.11,3792.8 ; U6.6@5020.95,3706.2 v11@5020.95,3772.8
  Signal Layer 2 w10: v1(2515,3545) 2755,3305 v1(2755,3010) v8(2755,2435.28) v8@2755,538.4 ; v1(2755,99.87) v8(2755.97,537.44)
  Signal Layer 4 w10: v7(1575,2720) 1575,2980.18 1604.82,3010 v1(2755,3010) 4148.75,3010 4178.75,2980 v1(4178.75,2940) 4178.75,2877.32 4156.35,2854.92 v7(4021.35,2854.92)
  Bottom Layer w10: v1(1760.16,3950.94) 1787.56,3923.54 Q9.2@1814.57,3923.54 ; C38.2@1779.53,3662.2 1780.16,3662.83 1780.16,3680.94 1880.79,3680.94 v4(1881.42,3681.57) ; v1(2230.16,3920.94) 2235.28,3926.06 R46.1@2235.28,3963.39 ; C33.1@2327.72,3461.57 C57.2@2327.72,3400.94 v1(2360.16,3400.94) ; R72.1@3704.25,4127.56 v1@3731.31,4127.56 ; R85.1@3922.61,3420 R85.1@3926.54,3420 v1(3963.75,3420) ; R85.1@3925.76,3423.15 C64.1@3925.76,3480
  other v1: 920,2890 4573.75,3255 4428.75,3345 615.55,3348.58 462.98,3349.8 1120,3425 4038.75,3440 1595,3445 905,3485 1050,3490 1510,3500 2430,3505 1320,3575 2385,3575 3973.75,3595 4538.75,3600 3038.75,3650 3118.75,3650 1515,3660 4558.75,3695 2510,3705 4103.75,3725 3108.75,3760 2420,3845 5183.75,3910 940,3935 1040,3945 4233.75,3960 705,3975 1760,4020 1390,4055 1935,4065 3433.75,4065 2246.1,4105 4868.75,4105 4828.75,4130 2315,4160 345,4165 2240,4165 1235,4170 4568.75,4170 3875,4180 4615.17,4190 3610,4195 4343.75,4195 5253.75,4235 5370,4420 5440,4420 5510,4420 5371.19,4477.63 5437.69,4477.63 5511.19,4477.63
  other v4: 1881.42,3563.46 1920.79,3563.46 1960.16,3563.46 1999.53,3563.46 2038.9,3563.46 3475.01,3571.26 3514.38,3571.26 3553.75,3571.26 3593.12,3571.26 3632.49,3571.26 1881.42,3602.83 1920.79,3602.83 1960.16,3602.83 1999.53,3602.83 2038.9,3602.83 3475.01,3610.63 3514.38,3610.63 3553.75,3610.63 3593.12,3610.63 3632.49,3610.63 1881.42,3642.2 1920.79,3642.2 1960.16,3642.2 1999.53,3642.2 2038.9,3642.2 3475.01,3650 3514.38,3650 3593.12,3650 3632.49,3650 1920.79,3681.57 1960.16,3681.57 1999.53,3681.57 2038.9,3681.57 3475.01,3689.37 3514.38,3689.37 3553.75,3689.37 3593.12,3689.37 3632.49,3689.37 1881.42,3720.94 1920.79,3720.94 1960.16,3720.94 1999.53,3720.94 2038.9,3720.94 3475.01,3728.74 3514.38,3728.74 3553.75,3728.74 3593.12,3728.74 3632.49,3728.74
  other v11: 5018.75,3775
  other v12: 1520,3815
COMP11: C33.2 C34.2 D11.2 U9.26 | length 988.6
  Top Layer w10: U9.26@2122.56,3553.62 2157.48,3553.62 v1@2242.83,3468.27
  Top Layer w20: D11.2@2513.78,3980.94 v1(2550.16,3980.94)
  Signal Layer 4 w10: v1(2250.16,3460.94) 2510.16,3460.94 2550.16,3500.94 v1(2550.16,3980.94)
COMP12: C64.2 C65.2 D17.2 U16.26 | length 797.9
  Top Layer w10: U16.26@3716.15,3561.42 3762.33,3561.42 v1(3843.75,3480) ; D17.2@3993.75,3936.69 3993.75,3910 v1(4003.75,3900)
  Top Layer w24: v1(3843.75,3480) C65.2@3870.64,3480
  Signal Layer 4 w10: v1(3843.75,3480) 3938.75,3480 4003.75,3545 v1(4003.75,3900)
  Bottom Layer w24: v1(3843.75,3480) C64.2@3870.64,3480
COMP21: C54.1 C58.1 D10.2 U9.11 | length 1356.4
  Top Layer w10: v1(1645.16,3435.94) 1643.29,3437.81 1643.29,3492.87 1637.72,3498.45 1637.72,3550.94 1642.79,3545.87 1734.24,3545.87 1741.99,3553.62 U9.11@1797.76,3553.62
  Signal Layer 4 w10: v1@1610.16,4150.94 v1@1613.92,4147.19 ; v1@1615.28,4148.56 1615.28,3660.64 1645.16,3630.77 v1(1645.16,3435.94)
  Bottom Layer w10: v1@1615.28,4145.82 1615.69,4146.22 D10.2@1957.8,4146.22
  other v1: 1615.16,4148.68
COMP22: C85.1 C88.1 D16.2 U16.11 | length 1108.6
  Top Layer w10: v1(3153.75,3455) 3170.56,3455 3215.56,3500 C85.1@3215.56,3553.11 ; C85.1@3216.86,3554.41 3226.14,3545.13 3344.05,3545.13 3360.34,3561.42 U16.11@3391.35,3561.42
  Signal Layer 4 w10: v1(3153.75,3455) 3153.75,3995 3183.75,4025 v1@3303.75,4025
  Bottom Layer w10: v1(3303.75,4022.74) 3390.15,4022.74 D16.2@3390.94,4021.95
CS1A1: C51.2 C53.1 R103.1 U9.1 | length 252.8
  Top Layer w10: C53.1@1578.5,3768.11 C51.2@1628.5,3768.11 1662.99,3768.11 1680.63,3750.47 U9.1@1797.76,3750.47
  Bottom Layer w10: R103.1@1633.9,3770.94 v1(1660.16,3770.94)
CS1A2: C70.1 C71.1 R116.1 U16.36 | length 262.3
  Top Layer w10: U16.36@3716.15,3758.27 3812.02,3758.27 v1(3844.1,3790.35) C70.1@3876.55,3790.35 C71.1@3926.55,3790.35
  Bottom Layer w10: v1(3844.1,3790.35) 3846.54,3792.8 R116.1@3881.74,3792.8
CS1B1: C51.1 C52.1 R102.1 U9.2 | length 235.4
  Top Layer w10: C52.1@1578.5,3712.99 C51.1@1628.5,3712.99 ; C51.1@1641.06,3717.99 v1@1669.76,3717.99 ; v1(1669.21,3720) 1680,3730.79 U9.2@1797.76,3730.79
  Bottom Layer w10: R102.1@1646.06,3717.99 v1@1669.76,3717.99
CS1B2: C70.2 C72.1 R117.1 U16.35 | length 252.8
  Top Layer w10: U16.35@3716.15,3738.58 3873.2,3738.58 C70.2@3876.55,3735.24 ; C70.2@3878.99,3732.8 C72.1@3928.99,3732.8
  Bottom Layer w10: v1(3843.75,3740) 3850.95,3732.8 R117.1@3881.74,3732.8
CS2A1: C39.1 C40.1 R93.1 U9.36 | length 218.9
  Top Layer w10: U9.36@2122.56,3750.47 2240.16,3750.47 v1(2259.49,3770.94) ; C39.1@2282.6,3772.2 C40.1@2332.6,3772.2
  Bottom Layer w10: v1(2259.49,3770.94) R93.1@2282.6,3770.94
CS2A2: C82.2 C84.1 R126.1 U16.1 | length 247.7
  Top Layer w10: C84.1@3184.1,3792.8 C82.2@3234.1,3792.8 ; C82.2@3236.54,3790.36 3278.39,3790.36 3310.48,3758.27 U16.1@3391.35,3758.27
  Bottom Layer w10: R126.1@3234.15,3790 v1@3263.75,3790
  other v1: 3273.75,3790
CS2B1: C39.2 C41.1 R92.1 U9.35 | length 194.6
  Top Layer w10: U9.35@2122.56,3730.79 2240.16,3730.79 v1(2261.48,3714.15) ; C39.2@2280.16,3714.65 C41.1@2330.16,3714.65
CS2B2: C82.1 C83.1 R127.1 U16.2 | length 235.4
  Top Layer w10: C83.1@3186.54,3735.24 C82.1@3236.54,3735.24 ; C82.1@3239.89,3738.58 U16.2@3391.35,3738.58
  Bottom Layer w10: R127.1@3238.55,3740 v1(3272.49,3740)
DIR1: J1.8 Q4.1 Q9.1 U2.4 U2.12 U9.44 | length 4820.7
  Top Layer w10: J1.8@455,3110 500,3155 500,3352.13 Q4.1@539.25,3391.38 ; U2.4@485,4112.6 v1@485,4230 ; v1(535,3790) U2.12@535,3898.03 ; U9.44@1930.63,3804.61 v1@1930.63,3860.47
  Signal Layer 2 w10: J1.8@455,3110 455,3152.82 414.57,3193.25 414.57,3230.43 374.63,3270.37 284.9,3270.37 210.28,3345 210.28,4324.72 280.68,4395.13 485,4395.09 v6(1905.28,4394.84)
  Signal Layer 4 w10: v1(210,3790) v1(535,3790) v1@540,3790 ; v1@485,4230 v1(485,4395) ; v6(1905.28,4394.84) 1905.28,3920.64 1930.16,3895.77 v1(1930.16,3860.94)
  Bottom Layer w10: Q9.1@1865.75,3925.35 v1(1930.16,3860.94)
  other v1: 485,4235
DIR2: Q3.1 Q9.3 R51.1 U2.1 U2.9 U16.44 | length 5457.2
  Top Layer w10: v1(280,3845) 370,3845 385,3860 U2.9@385,3898.03 ; v1(360,3390) Q3.1@387.87,3390 ; U2.1@635,4112.6 v1(635,4235) ; U16.44@3524.22,3812.4 3524.22,3890.47 v1(3533.75,3900)
  Signal Layer 2 w10: v1@357.76,3390 305,3390 270.75,3424.25 270.75,4270 315.75,4315 v1(635,4315) v1(3548.62,4315)
  Signal Layer 4 w10: v1(635,4235) v1(635,4315) ; v1(1825.16,4115.94) v6(1825.16,4314.84) ; v1(3533.75,3900) 3533.75,4044.82 3548.62,4059.7 v1(3548.62,4315)
  Bottom Layer w10: v1@1825.97,4115.13 R51.1@1825.97,4068.2 1825.97,4012.54 Q9.3@1840.16,3998.35
EN1: J1.2 U2.2 U2.5 U2.10 U2.13 U9.39 U16.39 | length 7586.8
  Top Layer w10: v1(435,3845) U2.10@435,3898.03 ; U2.5@435,4112.6 v1(435,4210) ; v1(585,3845) U2.13@585,3898.03 ; U2.2@585,4112.6 v1(585,4210) ; U9.39@2029.06,3804.61 2029.06,3854.67 2045.03,3870.64 2045.03,3905.82 v1(2050.16,3910.94) ; U16.39@3622.65,3812.4 3622.65,3868.9 v1(3633.75,3880)
  Signal Layer 2 w10: J1.2@255,3110 159.87,3205.13 159.87,4324.87 280.13,4445.13 v1(745,4445.13) 2369.87,4445.13 2370,4445 3259.87,4444.87 v1@3638.5,4444.87
  Signal Layer 4 w10: v1(435,3845) v1(585,3845) 712.6,3845 745,3877.4 745,4210 ; v1@439.87,4205.13 v1(435,4210) v1(585,4210) ; v1@580.13,4205.13 v1(585,4210) ; v1(745,4445.13) 745,4210 ; v1(2050.16,3910.94) v6(2050.16,4444.84) ; v1(3633.75,3880) 3638.62,3884.87 v1(3638.62,4445) ; v1(585,4210) 745,4210
EN2: J1.5 U9.43 U16.43 | length 5957.4
  Top Layer w10: U9.43@1950.31,3804.61 1950.31,3840.31 ; 1951.22,3841.22 1960.16,3850.16 v1(1960.16,3890.94) ; U16.43@3543.91,3812.4 3543.91,3860.16 v1(3553.75,3870)
  Signal Layer 2 w10: J1.5@355,3110 314.57,3150.43 314.57,3215.43 177.75,3352.25 177.75,4317.47 280.28,4420 v1(3573.75,4420)
  Signal Layer 4 w10: v1(1960.16,3890.94) v1(1960.16,4419.84) ; v1(3553.75,3870) 3573.75,3890 v1(3573.75,4420)
HO11: R94.1 R98.1 U9.15 | length 2187.2
  Top Layer w10: v1@1891.26,3422.05 U9.15@1891.26,3479.8
  Top Layer w24: R98.1@2280,2110 v5(2335,2110) ; R94.1@2280,2455 v2(2509.38,2455)
  Signal Layer 2 w24: v1(1890.16,3420.94) 1860,3390.79 1860,3350.79 1915.79,3295 2096.72,3295 2514.38,2877.34 2514.38,2169.38 2455,2110 v5(2335,2110)
HO12: R118.1 R122.1 U16.22 | length 1859.2
  Top Layer w10: U16.22@3622.65,3487.6 3622.65,3436.28 3653.75,3405.18 v1(3653.75,3400)
  Top Layer w24: v5(3050,2470) 3179.06,2470 3184.06,2465 R122.1@3193.75,2474.68 ; v5(3050,2815) R118.1@3295,2815
  Signal Layer 2 w24: v5@3048.75,2471.25 3048.75,2965 3249.37,3165.63 3564.45,3165.63 3635.62,3236.8 3635.62,3381.87 v1(3653.75,3400)
HO21: R106.1 R110.1 U9.22 | length 4068.8
  Top Layer w10: 2029.06,3417.22 U9.22@2029.06,3479.8 ; v1(2050.16,3390.94) v1@2050.16,3396.12
  Top Layer w15: 2029.06,3417.22 v1@2050.16,3396.12
  Top Layer w24: R106.1@2295,230 v5(2350,230) ; R110.1@2295,585 2532.48,585 v2(2535,587.52)
  Signal Layer 2 w24: v1(2050.16,3390.94) 2194.13,3390.94 2224.2,3360.87 2229.86,3360.87 2250.87,3339.86 2250.87,3334.2 2650,2935.08 2650,2120.39 2526.87,1997.27 2526.87,315 2441.87,230 v5(2350,230)
HO22: R130.1 R134.1 U16.15 | length 3770.7
  Top Layer w10: v1(3443.75,3390) 3443.75,3395.28 3484.85,3436.38 U16.15@3484.85,3487.6
  Top Layer w24: v2(3095,950) R130.1@3335,950 ; v2(3275,595) R134.1@3345,595
  Signal Layer 2 w24: v1(3256.21,3387.54) 2910,3041.33 2910,2144.77 3103.13,1951.64 3103.13,646.8 3150.92,599 3226,599 3230,595 v2(3275,595)
  Signal Layer 4 w24: v1(3256.21,3387.54) 3258.67,3390 v1(3443.75,3390)
IOUT11: C35.1 R43.2 U9.37 | length 248.5
  Top Layer w10: U9.37@2068.43,3804.61 2068.43,3838.43 2140.16,3910.16 C35.1@2140.16,3963.39 R43.2@2200.16,3963.39
IOUT12: C67.1 R69.2 U16.37 | length 232.7
  Top Layer w10: U16.37@3662.02,3812.4 3662.02,3842.99 v1@3759.03,3940 ; v1(3763.75,3940) R69.2@3763.75,3972.44
  Bottom Layer w10: v1(3763.75,3940) C67.1@3763.75,3972.44
IOUT21: C59.1 R41.2 U9.38 | length 203
  Top Layer w10: U9.38@2048.74,3804.61 2048.74,3848.74 ; 2049.65,3849.65 2080.16,3880.16 v1(2080.16,3930.94) C59.1@2080.16,3963.39
  Bottom Layer w10: v1(2080.16,3930.94) R41.2@2080.16,3963.39
IOUT22: C89.1 R67.2 U16.38 | length 222.1
  Top Layer w10: U16.38@3642.33,3812.4 3642.33,3848.58 3704.24,3910.5 C89.1@3704.24,3972.44
  Bottom Layer w10: v1(3703.75,3935.55) R67.2@3703.75,3971.94
ISETA1: C49.1 R7.2 R10.1 U9.45 | length 803.3
  Top Layer w10: 1390.83,3927.76 v1(1435,3927.76) ; U9.45@1910.94,3804.61 1910.94,3840.16 1895.36,3855.74 1895.36,3930.48 C49.1@1929.53,3964.65 v1@1929.53,3931.57
  Top Layer w30: R7.2@1390,3901.99 R10.1@1390,3951.87
  Signal Layer 2 w10: v1@1436.68,3926.07 1925.28,3926.07 v1(1930.16,3930.94)
ISETA2: C79.1 R22.2 R25.1 U16.45 | length 969.3
  Top Layer w10: U16.45@3504.54,3812.4 3504.54,3953.23 C79.1@3523.75,3972.44 ; v1(4168.75,3870) R25.1@4201.98,3870 ; R22.2@4202.29,3820.08 R22.2@4205.36,3817.01
  Top Layer w20: R22.2@4205.36,3817.01 R25.1@4205.36,3866.89
  Signal Layer 2 w10: v1@3503.75,3953.35 3521.07,3970.67 4068.08,3970.67 v1(4168.75,3870)
  other v1: 3508.75,3950
LO11: R95.1 R96.1 U9.17 | length 2692.1
  Top Layer w10: v1(1900,3375) 1900,3384.78 1925.28,3410.07 1925.28,3446.82 1930.63,3452.16 U9.17@1930.63,3479.8
  Top Layer w24: v2(1775,1920) R96.1@1775,1980 ; v5(2120,1920) R95.1@2120,1975
  Signal Layer 2 w24: v2(1775,1920) v5(2120,1920) 2314.38,1920 2554.38,2160 2554.38,2882.42 2109.6,3327.2 1947.8,3327.2 v1(1900,3375)
LO12: R119.1 R120.1 U16.20 | length 3023.3
  Top Layer w10: U16.20@3583.28,3487.6 3583.28,3460.47 3603.75,3440 v1(3603.75,3420)
  Top Layer w24: v5(3710,1965) R120.1@3710,2015 ; v5(4080,1965) R119.1@4080,2020
  Signal Layer 2 w24: v1(3603.75,3420) 3603.75,3250 3551.25,3197.5 3216.25,3197.5 3008.75,2990 3008.75,2181.25 3225,1965 v5(3710,1965) v5(4080,1965)
LO21: R107.1 R108.1 U9.20 | length 3663.4
  Top Layer w10: U9.20@1989.69,3479.8 1989.69,3451.42 1996.57,3444.53 1996.57,3414.53
  Top Layer w15: 1996.57,3414.53 2013.16,3397.94 v1(2013.16,3360.94)
  Top Layer w24: R108.1@1505,1128.29 v5@1505,1168.29 ; R107.1@1875,1125 v5@1875,1170
  Signal Layer 2 w24: v5(1505,1175) 1506.87,1176.87 2386.87,1176.87 2463.13,1253.13 2463.13,2023.67 2586.25,2146.8 2586.25,2895.62 2122.8,3359.07 2015.03,3359.07 v1(2013.16,3360.94)
  other v5: 1875,1175
LO22: R131.1 R132.1 U16.17 | length 3526.6
  Top Layer w10: v1(3483.75,3380) 3483.75,3410 3518.87,3445.13 3518.87,3445.89 3524.22,3451.24 U16.17@3524.22,3487.6
  Top Layer w24: R132.1@3495,1060 v5(3495,1125) ; R131.1@3850,1065 v5(3850,1125)
  Signal Layer 2 w24: v1(3483.75,3380) 3478.82,3380 3456.95,3358.13 3316.95,3358.13 2973.75,3014.92 2973.75,2171.18 3166.87,1978.05 3166.87,1188.13 3230,1125 v5(3495,1125) v5(3850,1125)
"NetA to B_1": "A to B.1" Q3.3 | length 91.3
  Top Layer w20: Q3.3@424.63,3485.67 424.63,3576.93
"NetA to B_2": "A to B.2" R13.2 | length 50.9
  Top Layer w20: 424.63,3639.92 R13.2@424.63,3690.86
"NetB to A_1": "B to A.1" Q4.3 | length 91.3
  Top Layer w20: Q4.3@577.2,3484.44 577.2,3575.7
"NetB to A_2": "B to A.2" R15.2 | length 50.9
  Top Layer w20: 577.2,3638.7 R15.2@577.2,3689.64
NetC2_1: C2.1 C4.1 D1.2 U1.1 | length 185
  Top Layer w20: C4.1@1290.94,3995 1240.94,3995 1240.94,3933.54 1255.71,3948.31 D1.2@1308.39,3948.31
NetC2_2: C2.2 R1.2 R3.2 R5.2 U1.2 | length 244.6
  Top Layer w20: U1.2@1174.68,3917.28 1174.68,3983.86 1185.83,3995 1185.83,4050 R3.2@1185.83,4108.58 ; R3.2@1192.13,4110 R1.2@1240.83,4110
NetC3_1: C3.1 R2.1 R4.2 R6.1 U1.6 | length 233.6
  Top Layer w20: R6.1@1120.94,3574.88 1120.94,3520 R2.1@1175.83,3520 ; R6.1@1122.13,3576.3 C3.1@1122.13,3630 ; C3.1@1124.68,3632.56 U1.6@1124.68,3702.72
NetC3_2: C3.2 C5.1 D2.2 U1.7 | length 289.9
  Top Layer w20: U1.7@1174.68,3702.72 1174.68,3632.56 C5.1@1223.39,3632.56 ; v1(1285,3720) 1308.39,3696.61 D2.2@1308.39,3691.69
  Signal Layer 2 w10: v1(1175,3664.33) 1229.33,3664.33 v1(1285,3720)
NetC4_2: C4.2 R5.1 | length 49.9
  Top Layer w20: R5.1@1240.94,4050 C4.2@1290.83,4050
NetC5_2: C5.2 R6.2 | length 45
  Top Layer w20: R6.2@1175.94,3575 C5.2@1220.94,3575
NetC6_1: C6.1 R9.2 R11.2 U1.5 | length 233.8
  Top Layer w20: R11.2@1007.24,3690 985.75,3668.5 985.75,3633.62 979.68,3627.56 1057.24,3627.56 1074.68,3645 U1.5@1074.68,3702.72
NetC7_1: C7.1 R8.1 R12.2 U1.3 | length 205
  Top Layer w20: R12.2@1079.8,4077.44 1124.68,4077.44 U1.3@1124.68,3917.28
NetC10_1: C10.1 C12.1 D5.2 U4.1 | length 243.3
  Top Layer w20: D5.2@4299.06,3607.01 4324.06,3582.01 4324.06,3557.56 C10.1@4375.72,3557.56 ; C10.1@4379.06,3560.91 U4.1@4379.06,3692.72
NetC10_2: C10.2 R16.2 R18.2 R20.2 U4.2 | length 309.4
  Top Layer w20: R16.2@4373.82,3438.11 4428.82,3438.11 R20.2@4428.82,3502.8 ; R20.2@4429.06,3503.04 U4.2@4429.06,3692.72
NetC11_1: C11.1 R17.1 R19.2 R21.1 U4.6 | length 303.5
  Top Layer w20: R19.2@4386.62,4150.31 4436.62,4150.31 R21.1@4436.62,4090.31 ; R21.1@4441.62,4085.31 4441.62,4035.31 4441.62,4027.13 4479.06,3989.69 U4.6@4479.06,3907.28
NetC11_2: C11.2 C13.1 D6.2 U4.7 | length 496
  Top Layer w20: v1(4285,4030) 4331.31,4030 4334.06,4032.76 C11.2@4383.94,4032.76 ; D6.2@4299.06,3853.62 4299.06,3820.94 v1(4300,3820) ; C11.2@4386.5,4035.31 4386.5,4007.56 4429.06,3965 U4.7@4429.06,3907.28
  Signal Layer 4 w10: v1(4285,4030) 4285,3835 v1(4300,3820)
NetC12_2: C12.2 R20.1 | length 50.3
  Top Layer w20: C12.2@4324.06,3502.44 4324.42,3502.8 4373.7,3502.8 R20.1@4373.35,3502.44
NetC13_2: C13.2 R21.2 | length 45
  Top Layer w20: C13.2@4334.06,4087.87 R21.2@4379.06,4087.87
NetC14_1: C14.1 R24.2 R27.2 U4.5 | length 340.1
  Top Layer w10: R24.2@4636.5,3985.31 R27.2@4636.5,4039.69
  Top Layer w20: 4491.27,4035.24 C14.1@4553.71,4035.24 ; U4.5@4529.06,3907.28 4529.06,4010.6 C14.1@4553.71,4035.24 ; R27.2@4636.82,4040 4558.47,4040 C14.1@4553.71,4035.24
NetC15_1: C15.1 R23.1 R28.2 U4.3 | length 367.4
  Top Layer w20: R28.2@4479.06,3512.56 U4.3@4479.06,3692.72 ; 4480.36,3646.3 4614.38,3646.3 C15.1@4614.38,3650 ; R28.2@4486.62,3505 R23.1@4536.19,3505
NetC21_1: C21.1 D9.1 L1.1 Q7.2 U6.20 | length 1128.7
  Top Layer w10: U6.20@5148.91,3481.8 5148.91,3424.84 5188.75,3385 5188.75,3318.83 v1@5188.75,3240
  Signal Layer 2 w10: v1(4823.75,2910) 4763.87,2850.13 4763.87,2799.7 4778.44,2785.13 4900.4,2785.13 5007.87,2892.6 5007.87,3097.68 5140.19,3230 v1(5188.75,3230)
  other v1: 4918.75,2940 4808.75,2950 4918.75,2990 4808.75,2997.5 4808.75,3045 4918.75,3045 4723.75,3080 4773.75,3080 4828.75,3080 4893.75,3080
NetC21_2: C21.2 U6.18 | length 167.5
  Top Layer w10: U6.18@5097.72,3481.8 5097.72,3329.86 C21.2@5108.75,3318.83
NetC24_1: C24.1 R35.2 R36.2 R37.1 U6.8 | length 447.6
  Top Layer w10: R35.2@4788.75,3664.51 4788.75,3709.39 C24.1@4781.19,3716.95 4781.19,3757.44 4853.75,3830 R37.1@4853.75,3852.44 R36.2@4908.75,3852.44 4969.77,3791.42 U6.8@4969.77,3706.2
NetC24_2: C24.2 C29.2 U6.9 | length 292.5
  Top Layer w10: C29.2@4836.31,3676.95 C24.2@4836.31,3716.95 4836.31,3777.56 4853.75,3795 4923.75,3795 4944.18,3774.57 U6.9@4944.18,3706.2
NetC25_1: C25.1 U6.7 | length 158.7
  Top Layer w10: C25.1@4963.75,3851.44 4995.36,3819.83 4995.36,3785.87 4994.87,3785.38 4994.87,3765.11 4995.36,3764.62 U6.7@4995.36,3706.2
NetC26_1: C26.1 R32.2 U6.5 | length 186.1
  Top Layer w10: C26.1@5023.75,3851.44 5023.75,3824 5042.87,3804.87 5042.87,3709.87 U6.5@5046.54,3706.2
  Bottom Layer w10: v1(5023.75,3820) R32.2@5023.75,3851.44
NetC27_1: C27.1 U6.17 | length 152.2
  Top Layer w10: C27.1@5043.75,3341.39 5072.13,3369.78 U6.17@5072.13,3481.8
NetC29_1: C29.1 R35.1 | length 60
  Top Layer w10: R35.1@4788.75,3609.39 C29.1@4848.75,3609.39
NetC30_1: C30.1 R41.1 R46.2 U7.1 | length 179.5
  Bottom Layer w10: C30.1@2095,4047.44 2107.4,4035.04 U7.1@2151.59,4035.04 2151.59,3975.77 R41.1@2139.21,3963.39 R46.2@2176.22,3963.39 R46.2@2180.16,3963.39
NetC30_2: C30.2 D10.1 R40.2 U7.2 | length 199.2
  Bottom Layer w10: R40.2@2037.56,4070 2070.12,4102.56 C30.2@2095,4102.56 ; D10.1@2044.41,4146.22 2051.34,4146.22 C30.2@2095,4102.56 ; U7.2@2151.59,4109.84 2102.28,4109.84 C30.2@2095,4102.56
NetC31_1: C31.1 R43.1 R47.2 U8.1 | length 208.8
  Top Layer w10: R43.1@2200.16,4018.5 R43.1@2200.16,4022.44 R47.2@2200.16,4104.59 ; R43.1@2202.8,4022.76 U8.1@2277.6,4022.76 C31.1@2277.6,3974.84
NetC31_2: C31.2 D11.1 R42.2 U8.2 | length 222.7
  Top Layer w10: C31.2@2342.56,3965 C31.2@2352.4,3974.84 ; U8.2@2352.4,4022.76 C31.2@2352.4,3974.84 ; R42.2@2431.74,4063.01 2426.85,4058.12 D11.1@2426.85,3981.26 2358.82,3981.26 C31.2@2352.4,3974.84
NetC32_1: C32.1 R39.2 U9.28 | length 244.9
  Top Layer w10: U9.28@2122.56,3592.99 2168.67,3592.99 2190.74,3570.92 2206.78,3554.87 2278.04,3554.87 2280.67,3552.24 ; R39.2@2280.67,3522.2 2280.67,3552.24 ; C32.1@2280.67,3592.09 2280.67,3582.2 2280.67,3552.24
NetC34_1: C34.1 R44.1 | length 44.9
  Top Layer w10: C34.1@2326.42,3462.2 R44.1@2371.3,3462.2
NetC36_1: C36.1 R45.2 U9.8 | length 158.7
  Top Layer w10: C36.1@1644.02,3624.65 R45.2@1690.16,3624.65 1756.46,3624.65 1768.43,3612.68 U9.8@1797.76,3612.68
NetC43_2: C43.2 R53.1 U9.23 | length 225.1
  Top Layer w10: U9.23@2048.74,3479.8 2048.74,3446.06 C43.2@2120.16,3374.65
  Top Layer w20: C43.2@2120.16,3374.65 2120.16,3319.45 R53.1@2145,3294.61
NetC48_1: C48.1 R58.1 U9.14 | length 231.4
  Top Layer w10: C48.1@1800.16,3374.65 1871.57,3446.06 U9.14@1871.57,3479.8
  Top Layer w20: R58.1@1760,3294.61 1800.16,3334.76 C48.1@1800.16,3374.65
NetC50_1: C50.1 U9.12 | length 171
  Top Layer w10: v1(1690.16,3490.94) 1710.16,3490.94 1753.15,3533.94 U9.12@1797.76,3533.94
  Bottom Layer w10: C50.1@1644.55,3490.94 v1(1690.16,3490.94)
NetC54_2: C54.2 R62.2 | length 39.8
  Top Layer w10: R62.2@1543.29,3552.2 1544.55,3550.94 C54.2@1582.6,3550.94
NetC56_1: C56.1 R60.2 U9.9 | length 321.4
  Top Layer w10: v1(1510.16,3590.94) 1512.2,3592.99 1711,3592.99 1713.63,3595.62 1734.24,3595.62 1736.87,3592.99 U9.9@1797.76,3592.99
  Bottom Layer w10: R60.2@1487.72,3610.95 1507.72,3590.94 v1(1510.16,3590.94)
NetC57_1: C57.1 R61.2 U9.25 | length 231.5
  Top Layer w10: U9.25@2122.56,3533.94 2151.06,3533.94 2223.74,3461.26 2223.74,3416.26 2233.66,3406.34 v1(2250.16,3406.34) 2255.55,3400.94 R61.2@2272.6,3400.94
NetC61_1: C61.1 R65.2 U16.28 | length 227.7
  Top Layer w10: U16.28@3716.15,3600.79 3773.52,3600.79 3799.3,3575 3871.19,3575 ; C61.1@3875.68,3600.79 C61.1@3876.19,3601.3 R65.2@3876.19,3540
